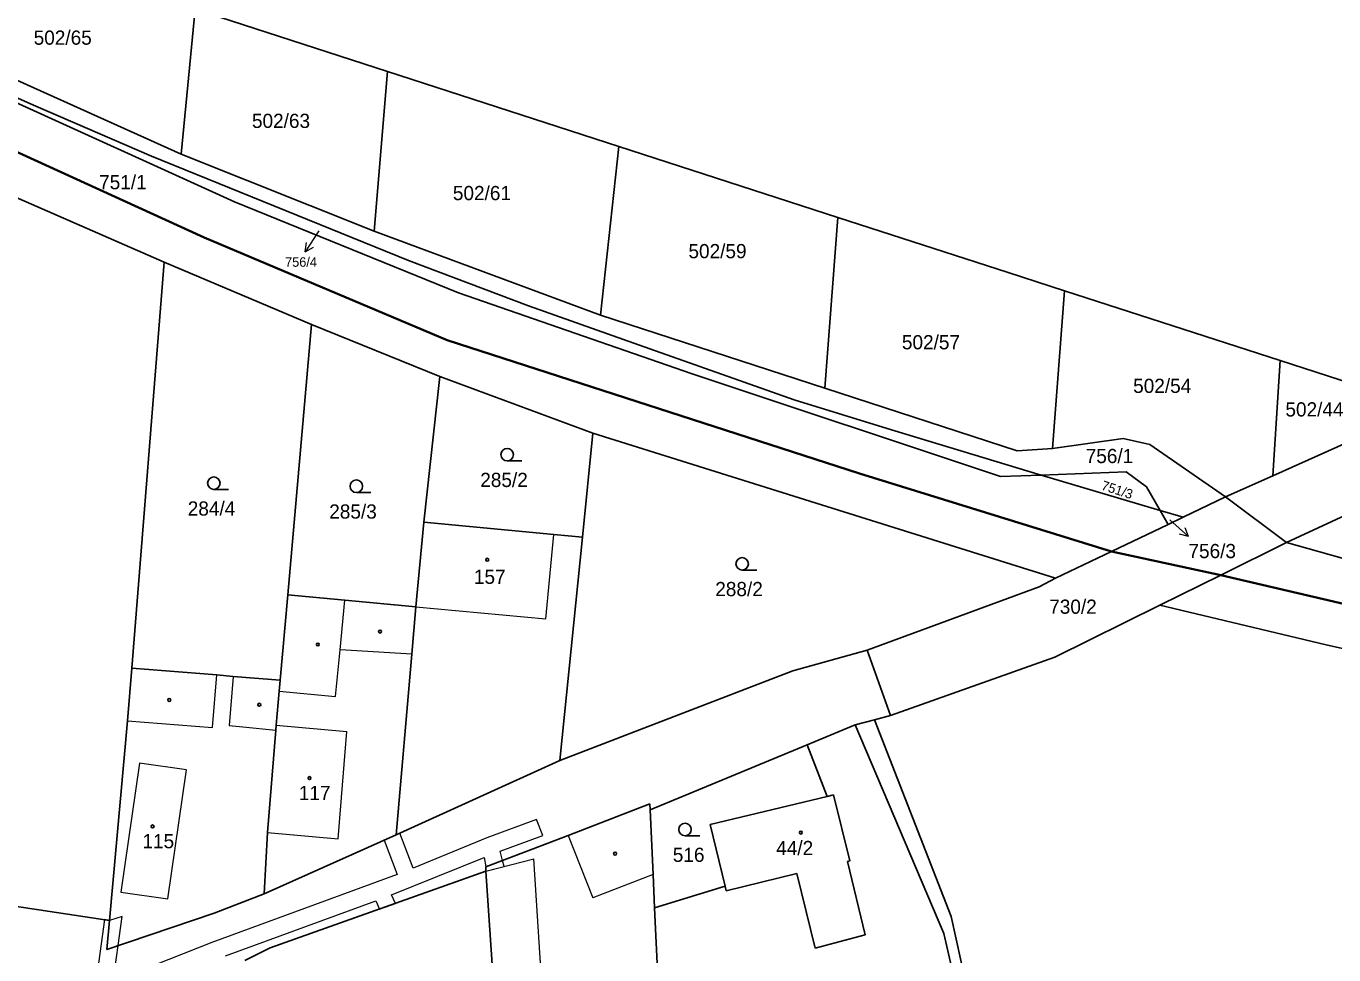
# Model space of a CAD drawing. Extents: x -701211 to -698780, y -1014269 to -1012378.
# Drawn here: x -700163.9 to -700007.4, y -1013027.3 to -1012916.2 of the extents above; entities that cross this region are included whole.
import ezdxf
from ezdxf.enums import TextEntityAlignment as Align

# ---------------------------------------------------------------- set-up
doc = ezdxf.new("R2010")
doc.units = 0
doc.header["$LTSCALE"] = 0.68
for name, color, linetype, lineweight in [('1', 7, 'Continuous', 25), ('13', 7, 'Continuous', 13), ('3', 7, 'Continuous', 25), ('4', 7, 'Continuous', 13), ('5', 7, 'Continuous', 25), ('6', 7, 'Continuous', 35), ('7', 7, 'Continuous', 13)]:
    doc.layers.add(name, color=color, linetype=linetype, lineweight=lineweight)
doc.layers.add('2', color=7, linetype='Continuous')

msp = doc.modelspace()

# ---------------------------------------------------------------- linework, layer by layer
at = {"layer": '1'}
for p, q in [((-700222.45, -1012899.25), (-700138.97, -1012937.2)), ((-700163.03, -1012925.62), (-700188.03, -1012914.54)), ((-700145.38, -1012931.48), (-700143.71, -1012914.11)), ((-700120.67, -1012921.58), (-700143.71, -1012914.11)), ((-700145.38, -1012931.48), (-700176.46, -1012917.48)), ((-700122.27, -1012940.69), (-700120.67, -1012921.58)), ((-700093, -1012930.55), (-700120.67, -1012921.58)), ((-700148.9, -1012931.73), (-700163.03, -1012925.62)), ((-700147.39, -1012944.42), (-700178.1, -1012931)), ((-700118.18, -1012944.22), (-700148.9, -1012931.73)), ((-700122.27, -1012940.69), (-700145.38, -1012931.48)), ((-700095.21, -1012950.74), (-700093, -1012930.55)), ((-700066.78, -1012939.05), (-700093, -1012930.55)), ((-700138.97, -1012937.2), (-700112.2, -1012948.09)), ((-700068.35, -1012959.48), (-700066.78, -1012939.05)), ((-700046.42, -1012945.66), (-700066.78, -1012939.05)), ((-700095.21, -1012950.74), (-700122.27, -1012940.69)), ((-700103.8, -1012949.64), (-700118.18, -1012944.22)), ((-700151.28, -1012993), (-700147.39, -1012944.42)), ((-700129.76, -1012951.86), (-700147.39, -1012944.42)), ((-700039.68, -1012947.84), (-700046.42, -1012945.66)), ((-700112.2, -1012948.09), (-700084.22, -1012957.77)), ((-700041.11, -1012966.71), (-700039.68, -1012947.84)), ((-700013.87, -1012956.19), (-700039.68, -1012947.84)), ((-700089.3, -1012954.77), (-700103.8, -1012949.64)), ((-700132.62, -1012984.22), (-700129.76, -1012951.86)), ((-700114.42, -1012958.07), (-700129.76, -1012951.86)), ((-700068.35, -1012959.48), (-700095.21, -1012950.74)), ((-700072, -1012960.87), (-700089.3, -1012954.77)), ((-700013.87, -1012956.19), (-700014.75, -1012969.97)), ((-699996.53, -1012961.8), (-700013.87, -1012956.19)), ((-700116.33, -1012975.53), (-700114.42, -1012958.07)), ((-700096.09, -1012964.88), (-700114.42, -1012958.07)), ((-700084.22, -1012957.77), (-700047.31, -1012970.07)), ((-700045.34, -1012966.99), (-700068.35, -1012959.48)), ((-700060.39, -1012964.48), (-700072, -1012960.87)), ((-699996.53, -1012961.8), (-700014.75, -1012969.97)), ((-700042.47, -1012969.89), (-700060.39, -1012964.48)), ((-700096.09, -1012964.88), (-700097.35, -1012977.3)), ((-700040.73, -1012982.23), (-700096.09, -1012964.88)), ((-700032.66, -1012965.49), (-700041.11, -1012966.71)), ((-700029.47, -1012966.24), (-700032.66, -1012965.49)), ((-700020.39, -1012972.5), (-700029.47, -1012966.24)), ((-700013.11, -1012977.97), (-699985.9, -1012965.26)), ((-700041.11, -1012966.71), (-700045.34, -1012966.99)), ((-700047.31, -1012970.07), (-700042.47, -1012969.89)), ((-700028.21, -1012974.13), (-700042.47, -1012969.89)), ((-700014.75, -1012969.97), (-700020.39, -1012972.5)), ((-700029.84, -1012971.29), (-700028.21, -1012974.13)), ((-700020.39, -1012972.5), (-700025.48, -1012974.94)), ((-700020.39, -1012972.5), (-700013.11, -1012977.97)), ((-700117.27, -1012985.65), (-700116.33, -1012975.53)), ((-700116.33, -1012975.53), (-700100.78, -1012976.98)), ((-700025.48, -1012974.94), (-700028.21, -1012974.13)), ((-700028.21, -1012974.13), (-700027.26, -1012975.79)), ((-700025.48, -1012974.94), (-700027.26, -1012975.79)), ((-700100.78, -1012976.98), (-700097.35, -1012977.3)), ((-700027.26, -1012975.79), (-700034.04, -1012979.03)), ((-700097.35, -1012977.3), (-700100.06, -1013004.03)), ((-700020.98, -1012981.86), (-700013.11, -1012977.97)), ((-700013.11, -1012977.97), (-699987.41, -1012985.18)), ((-700034.04, -1012979.03), (-700040.73, -1012982.23)), ((-700028.26, -1012985.46), (-700020.98, -1012981.86)), ((-700042.7, -1012983.27), (-700063.3, -1012990.82)), ((-700042.7, -1012983.27), (-700040.73, -1012982.23)), ((-700133.53, -1012994.42), (-700132.62, -1012984.22)), ((-700125.78, -1012984.86), (-700132.62, -1012984.22)), ((-700117.27, -1012985.65), (-700125.78, -1012984.86)), ((-700117.76, -1012991.31), (-700117.27, -1012985.65)), ((-700040.84, -1012991.66), (-700028.26, -1012985.46)), ((-700008.37, -1012990.22), (-700028.26, -1012985.46)), ((-700063.3, -1012990.82), (-700072.16, -1012993.31)), ((-700060.48, -1012998.67), (-700063.3, -1012990.82)), ((-699986.72, -1012995.01), (-700008.37, -1012990.22)), ((-700119.63, -1013012.94), (-700117.76, -1012991.31)), ((-700060.48, -1012998.67), (-700040.84, -1012991.66)), ((-700151.78, -1012999.29), (-700151.28, -1012993)), ((-700151.28, -1012993), (-700141.11, -1012993.81)), ((-700141.11, -1012993.81), (-700139.15, -1012993.97)), ((-700139.15, -1012993.97), (-700133.53, -1012994.42)), ((-700133.64, -1012995.75), (-700133.53, -1012994.42)), ((-700100.06, -1013004.03), (-700072.16, -1012993.31)), ((-700134, -1012999.83), (-700133.64, -1012995.75)), ((-700062.42, -1012999.17), (-700060.48, -1012998.67)), ((-700153.94, -1013023.17), (-700151.78, -1012999.29)), ((-700134.05, -1013000.43), (-700135.04, -1013012.67)), ((-700134, -1012999.83), (-700134.05, -1013000.43)), ((-700064.71, -1012999.76), (-700070.48, -1013002.15)), ((-700064.71, -1012999.76), (-700062.42, -1012999.17)), ((-700064.71, -1012999.76), (-700054.12, -1013024.75)), ((-700053.24, -1013022.73), (-700062.42, -1012999.17)), ((-700070.48, -1013002.15), (-700089.26, -1013009.96)), ((-700068.07, -1013008.34), (-700070.48, -1013002.15)), ((-700100.06, -1013004.03), (-700119.63, -1013012.94)), ((-700082.07, -1013011.7), (-700068.07, -1013008.34)), ((-700068.07, -1013008.34), (-700067.32, -1013008.16)), ((-700067.32, -1013008.16), (-700065.37, -1013016.04)), ((-700089.27, -1013009.21), (-700099.05, -1013013.01)), ((-700089.27, -1013009.21), (-700089.26, -1013009.96)), ((-700089.26, -1013009.96), (-700088.9, -1013017.67)), ((-700135.43, -1013019.98), (-700135.04, -1013012.67)), ((-700119.63, -1013012.94), (-700135.43, -1013019.98)), ((-700099.05, -1013013.01), (-700108.93, -1013016.78)), ((-700080.29, -1013019.08), (-700082.07, -1013011.7)), ((-700065.37, -1013016.04), (-700065.63, -1013016.11)), ((-700065.63, -1013016.11), (-700063.51, -1013024.91)), ((-700134.7, -1013026.48), (-700108.9, -1013017.28)), ((-700108.9, -1013017.28), (-700108.93, -1013016.78)), ((-700108.9, -1013017.28), (-700108.08, -1013029.61)), ((-700088.9, -1013017.67), (-700088.72, -1013021.67)), ((-700071.68, -1013017.57), (-700080.15, -1013019.65)), ((-700069.5, -1013026.51), (-700071.68, -1013017.57)), ((-700080.29, -1013019.08), (-700088.72, -1013021.67)), ((-700080.15, -1013019.65), (-700080.29, -1013019.08)), ((-700153.94, -1013023.17), (-700172, -1013020.45)), ((-700135.43, -1013019.98), (-700141.43, -1013022.32)), ((-700141.43, -1013022.32), (-700154.25, -1013026.64)), ((-700088.72, -1013021.67), (-700088.04, -1013036.26)), ((-700154.25, -1013026.64), (-700153.94, -1013023.17)), ((-700049.09, -1013041.5), (-700053.24, -1013022.73)), ((-700063.51, -1013024.91), (-700069.5, -1013026.51)), ((-700053.2, -1013028.72), (-700054.12, -1013024.75)), ((-700137.73, -1013027.96), (-700134.7, -1013026.48))]:
    msp.add_line(p, q, dxfattribs=at)
msp.add_lwpolyline([(-700042.47, -1012969.89), (-700032.28, -1012969.51), (-700029.84, -1012971.29)], dxfattribs=at)
at = {"layer": '13'}
msp.add_lwpolyline([(-700140.05, -1013027.41), (-700122.09, -1013020.82), (-700121.65, -1013021.83), (-700119.73, -1013021.14), (-700120.18, -1013020.12), (-700109.1, -1013015.66), (-700108.93, -1013016.78), (-700106.9, -1013016.01), (-700107.19, -1013014.9), (-700102.11, -1013013.02), (-700102.83, -1013011.09), (-700108.78, -1013013.3), (-700117.62, -1013016.94), (-700119.2, -1013012.74), (-700119.63, -1013012.94), (-700121.07, -1013013.58), (-700119.52, -1013017.68), (-700141.68, -1013025.81), (-700153.51, -1013030.48), (-700152.91, -1013026.19), (-700154.25, -1013026.64), (-700153.94, -1013023.17), (-700154.53, -1013023.08), (-700155.63, -1013030.93)], dxfattribs=at)
for points in [[(-700108.93, -1013016.78), (-700108.9, -1013017.28), (-700106.72, -1013016.72), (-700106.9, -1013016.01)], [(-700154.25, -1013026.64), (-700152.91, -1013026.19), (-700152.42, -1013022.72), (-700153.94, -1013023.17)]]:
    msp.add_lwpolyline(points, close=True, dxfattribs=at)
at = {"layer": '3'}
for p, q in [((-700106.353, -1012968.19), (-700104.603, -1012968.19)), ((-700141.453, -1012971.61), (-700139.703, -1012971.61)), ((-700124.403, -1012971.97), (-700122.653, -1012971.97)), ((-700078.243, -1012981.25), (-700076.493, -1012981.25)), ((-700085.073, -1013013.05), (-700083.323, -1013013.05))]:
    msp.add_line(p, q, dxfattribs=at)
for centre in [(-700106.3529, -1012967.4398), (-700141.4529, -1012970.8598), (-700124.4029, -1012971.2198), (-700078.2429, -1012980.4998), (-700085.0729, -1013012.2998)]:
    msp.add_circle(centre, 0.75, dxfattribs=at)
at = {"layer": '4'}
for p, q in [((-700101.72, -1012987.1), (-700100.78, -1012976.98)), ((-700126.36, -1012990.81), (-700125.78, -1012984.86)), ((-700117.27, -1012985.65), (-700101.72, -1012987.1)), ((-700126.9, -1012996.4), (-700126.36, -1012990.81)), ((-700117.76, -1012991.31), (-700126.36, -1012990.81)), ((-700141.61, -1013000.1), (-700141.11, -1012993.81)), ((-700139.15, -1012993.97), (-700139.61, -1012999.85)), ((-700133.64, -1012995.75), (-700126.9, -1012996.4)), ((-700151.78, -1012999.29), (-700141.61, -1013000.1)), ((-700139.61, -1012999.85), (-700138, -1013000.02)), ((-700138, -1013000.02), (-700134.05, -1013000.43)), ((-700134, -1012999.83), (-700125.55, -1013000.56)), ((-700126.59, -1013013.4), (-700125.55, -1013000.56)), ((-700150.36, -1013004.35), (-700152.6, -1013019.79)), ((-700144.71, -1013005.17), (-700150.36, -1013004.35)), ((-700146.95, -1013020.61), (-700144.71, -1013005.17)), ((-700135.04, -1013012.67), (-700126.59, -1013013.4)), ((-700099.05, -1013013.01), (-700096.09, -1013020.46)), ((-700108.9, -1013017.28), (-700103.17, -1013015.81)), ((-700102.21, -1013031.03), (-700103.17, -1013015.81)), ((-700088.9, -1013017.67), (-700096.09, -1013020.46)), ((-700152.6, -1013019.79), (-700146.95, -1013020.61))]:
    msp.add_line(p, q, dxfattribs=at)
at = {"layer": '5'}
for centre in [(-700108.7368, -1012980.0192), (-700121.5668, -1012988.6092), (-700129.0168, -1012990.1592), (-700146.7968, -1012996.7992), (-700136.0168, -1012997.3692), (-700130.0068, -1013006.1492), (-700148.7868, -1013011.9292), (-700071.2168, -1013012.6692), (-700093.4468, -1013015.1892)]:
    msp.add_circle(centre, 0.175, dxfattribs=at)
at = {"layer": '6'}
for p, q in [((-700205.65, -1012912.73), (-700142.6, -1012941.45)), ((-700142.6, -1012941.45), (-700113.54, -1012953.76)), ((-700113.54, -1012953.76), (-700064.2, -1012969.7)), ((-700064.2, -1012969.7), (-700034.04, -1012979.03)), ((-700034.04, -1012979.03), (-700020.98, -1012981.86)), ((-700020.98, -1012981.86), (-699978.65, -1012991.74))]:
    msp.add_line(p, q, dxfattribs=at)
at = {"layer": '7'}
for p, q in [((-700130.514, -1012943.177), (-700129.549, -1012942.61)), ((-700024.83, -1012977.248), (-700025.239, -1012976.206))]:
    msp.add_line(p, q, dxfattribs=at)
for points in [[(-700128.88, -1012940.66), (-700130.514, -1012943.177), (-700130.389, -1012942.064)], [(-700027.06, -1012975.24), (-700024.83, -1012977.248), (-700025.909, -1012976.95)]]:
    msp.add_lwpolyline(points, dxfattribs=at)

# ---------------------------------------------------------------- texts
at = {"layer": '2'}
for s, p in [('502/65', (-700159.54, -1012918.385)), ('502/63', (-700133.42, -1012928.345)), ('751/1', (-700152.34, -1012935.682)), ('502/61', (-700109.38, -1012936.985)), ('502/59', (-700081.19, -1012943.935)), ('502/57', (-700055.65, -1012954.835)), ('502/54', (-700027.98, -1012960.055)), ('502/44', (-700009.76, -1012962.875)), ('756/1', (-700034.29, -1012968.452))]:
    msp.add_text(s, height=1.7, dxfattribs=at).set_placement(p, align=Align.CENTER)
msp.add_text('756/4', height=1.139, dxfattribs=at).set_placement((-700129.12, -1012944.958), align=Align.RIGHT)
for s, p in [('285/2', (-700109.58, -1012971.315)), ('284/4', (-700144.58, -1012974.735)), ('285/3', (-700127.65, -1012975.095)), ('756/3', (-700024.84, -1012979.825)), ('157', (-700110.34, -1012982.905)), ('288/2', (-700081.46, -1012984.375)), ('730/2', (-700041.5, -1012986.485)), ('117', (-700131.29, -1013008.775)), ('115', (-700150, -1013014.545)), ('516', (-700086.54, -1013016.175)), ('44/2', (-700074.17, -1013015.365))]:
    msp.add_text(s, height=1.7, dxfattribs=at).set_placement(p)
msp.add_text('751/3', height=1.139, rotation=342, dxfattribs=at).set_placement((-700033.5385, -1012972.1892), align=Align.CENTER)

doc.saveas('drawing.dxf')
